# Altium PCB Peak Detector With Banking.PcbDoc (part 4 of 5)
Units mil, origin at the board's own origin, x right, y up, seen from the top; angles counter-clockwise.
Board outline 3330 x 2725 mil, 4 copper layers (TopLayer, GROUND, MidLayer1, BottomLayer); 549 components, 391 nets, 1594 pads, 460 vias.
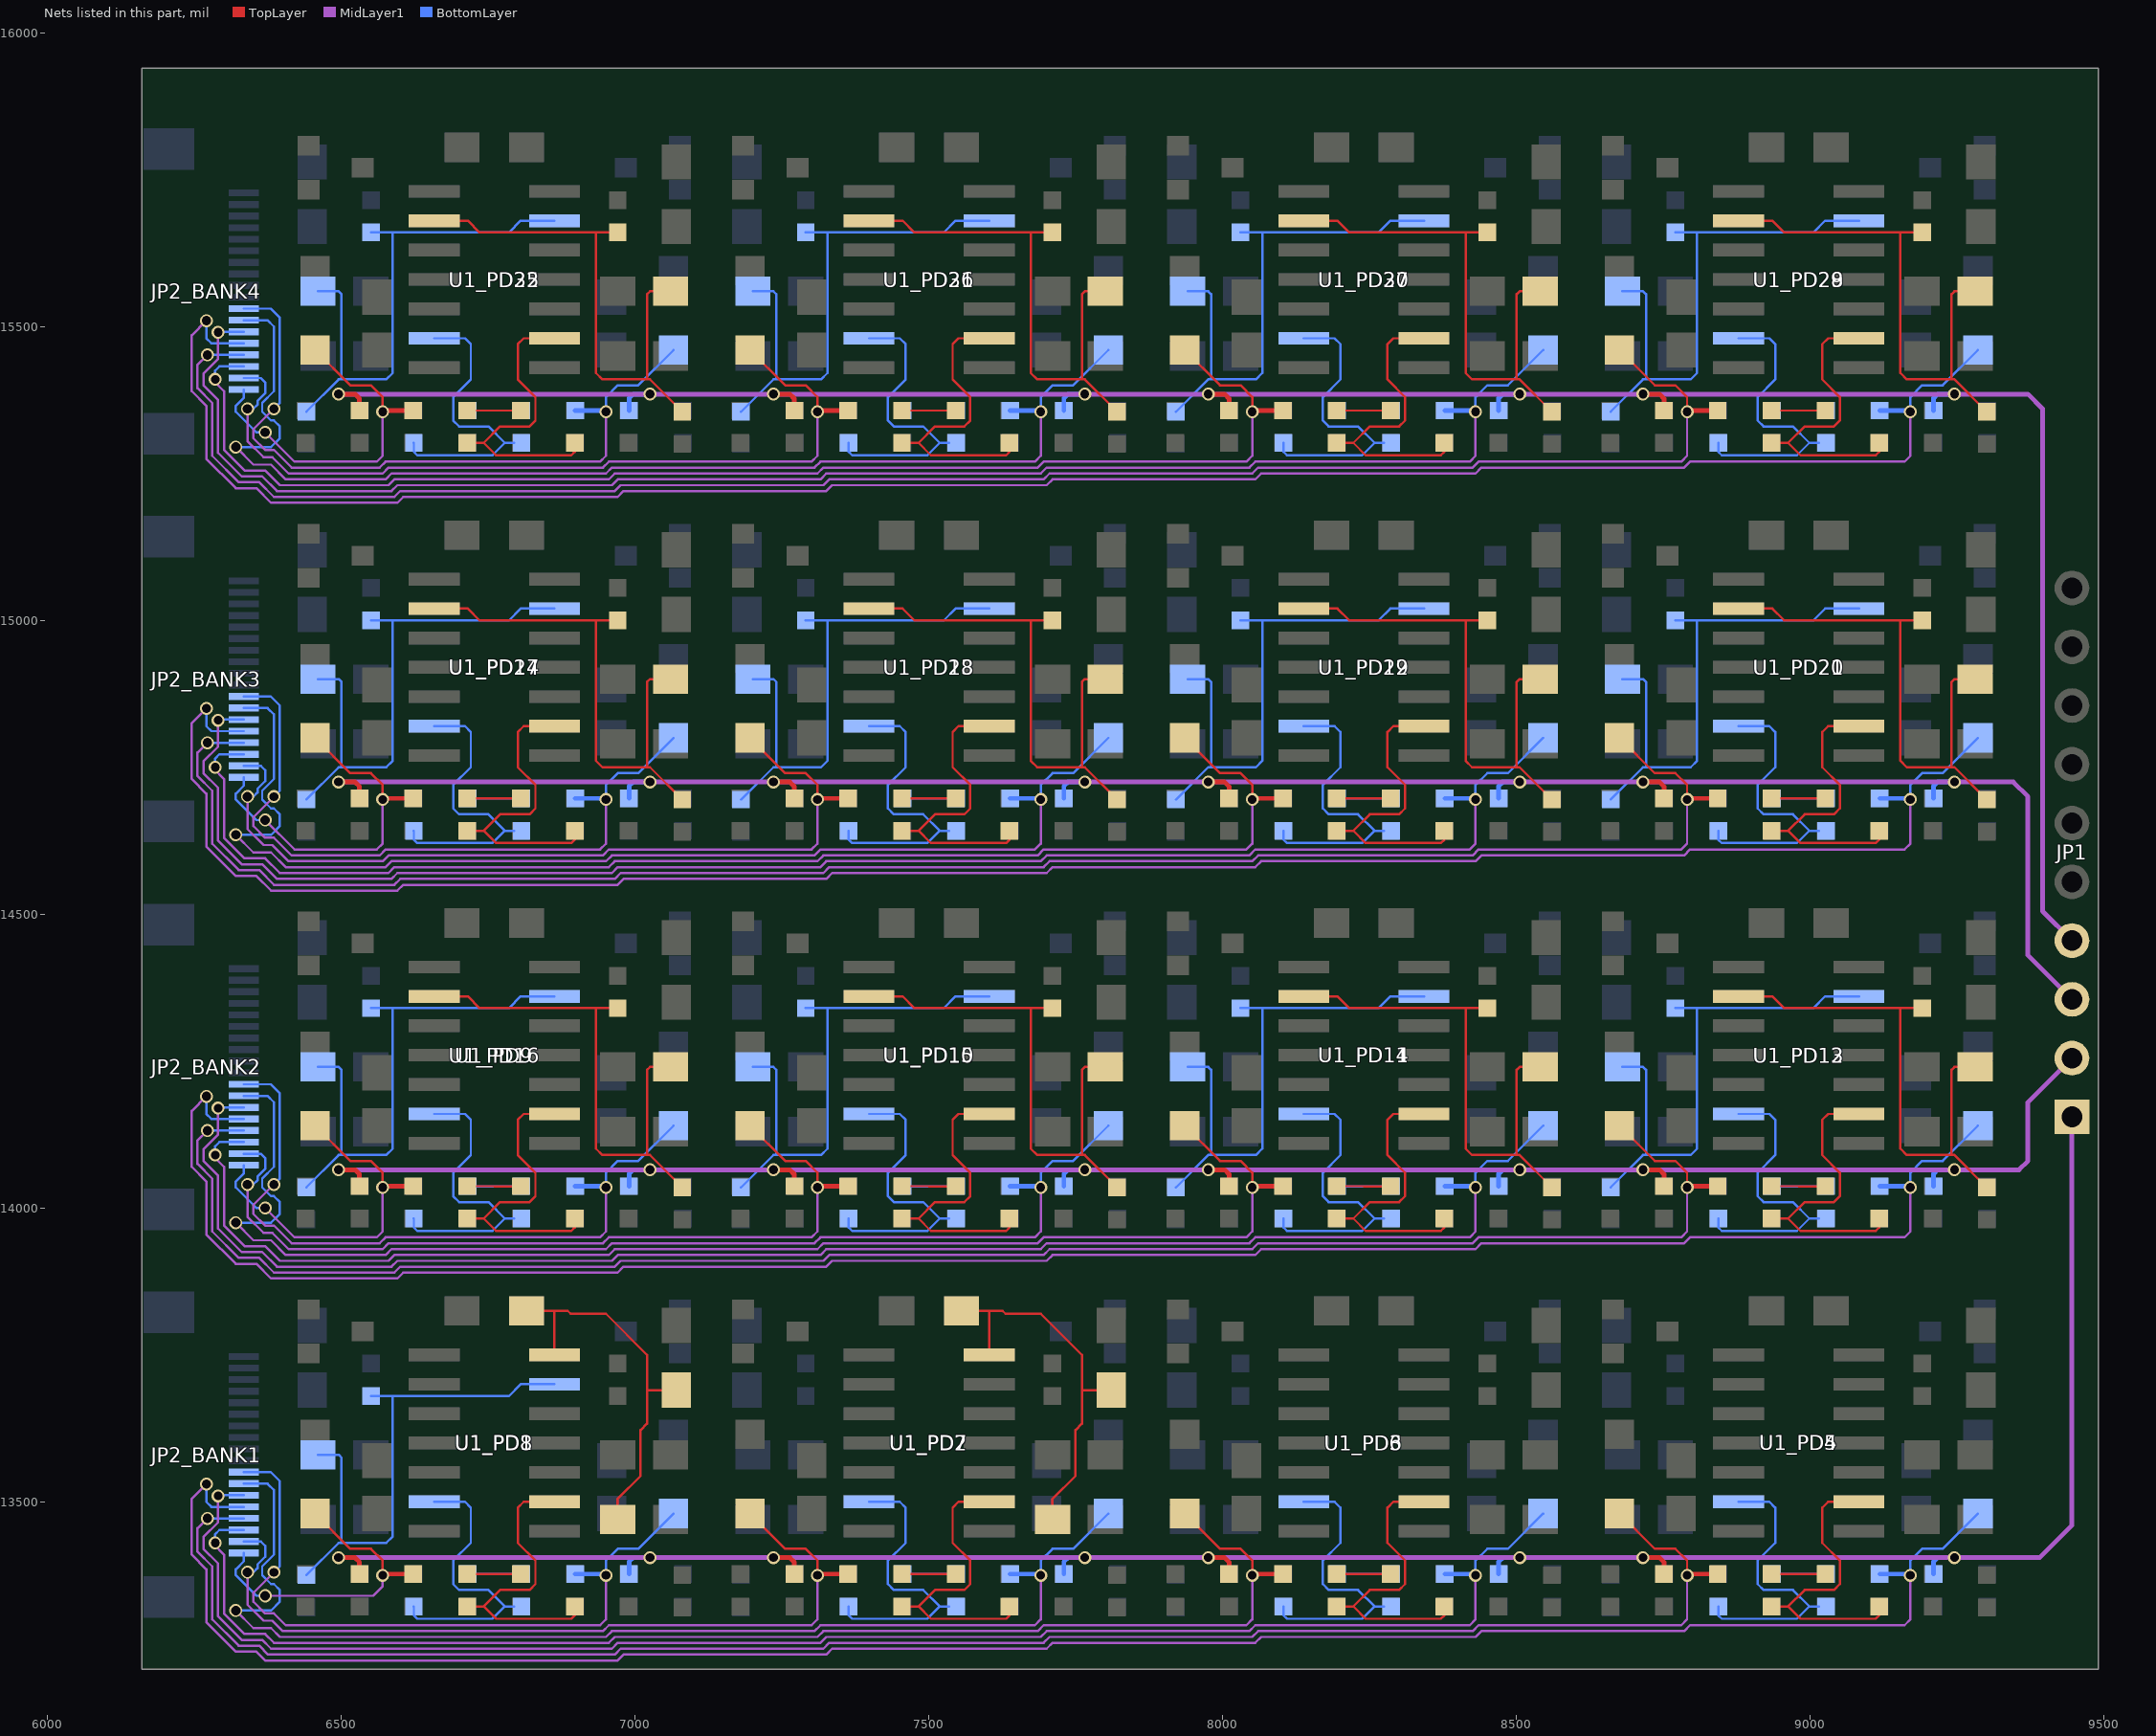
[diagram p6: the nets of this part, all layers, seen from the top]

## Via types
v1: diameter 22, hole 15, TopLayer to BottomLayer, 432 vias
v2: diameter 22, hole 16, TopLayer to BottomLayer, 28 vias

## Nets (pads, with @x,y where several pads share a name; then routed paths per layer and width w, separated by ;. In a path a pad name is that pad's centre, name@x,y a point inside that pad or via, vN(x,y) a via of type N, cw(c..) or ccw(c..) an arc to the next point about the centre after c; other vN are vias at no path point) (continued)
NetC5_PD8_2: C5_PD8.2 R8_PD8.2 R88_PD8.1 U1_PD8.9 | length 921.1
  BottomLayer w4: R8_PD8.2@6440,13375 6495,13430 6500,13430 ; C5_PD8.2@6459.99,13580 6495,13580 6500,13575 6500,13430 ; R88_PD8.1@6550,13680 6587,13680 ; U1_PD8.9@6862.37,13700 6805,13700 6785,13680 6587,13680 ; 6500,13430 6576,13430 6587,13441 6587,13680
NetC5_PD9_2: C5_PD9.2 R8_PD9.2 R88_PD9.1 U1_PD9.9 | length 921.1
  TopLayer w4: U1_PD9.9@6657.63,14360 6715,14360 6735,14340 6933,14340 ; R88_PD9.1@6970,14340 6933,14340 ; C5_PD9.2@7060.01,14240 7025,14240 7020,14235 7020,14090 ; R8_PD9.2@7080,14035 7025,14090 7020,14090 ; 6933,14340 6933,14101 6944,14090 7020,14090
NetC5_PD10_2: C5_PD10.2 R8_PD10.2 R88_PD10.1 U1_PD10.9 | length 921.1
  TopLayer w4: U1_PD10.9@7397.63,14360 7455,14360 7475,14340 7673,14340 ; R88_PD10.1@7710,14340 7673,14340 ; C5_PD10.2@7800.01,14240 7765,14240 7760,14235 7760,14090 ; R8_PD10.2@7820,14035 7765,14090 7760,14090 ; 7673,14340 7673,14101 7684,14090 7760,14090
NetC5_PD11_2: C5_PD11.2 R8_PD11.2 R88_PD11.1 U1_PD11.9 | length 921.1
  TopLayer w4: U1_PD11.9@8137.63,14360 8195,14360 8215,14340 8413,14340 ; R88_PD11.1@8450,14340 8413,14340 ; C5_PD11.2@8540.01,14240 8505,14240 8500,14235 8500,14090 ; R8_PD11.2@8560,14035 8505,14090 8500,14090 ; 8413,14340 8413,14101 8424,14090 8500,14090
NetC5_PD12_2: C5_PD12.2 R8_PD12.2 R88_PD12.1 U1_PD12.9 | length 921.1
  TopLayer w4: U1_PD12.9@8877.63,14360 8935,14360 8955,14340 9153,14340 ; R88_PD12.1@9190,14340 9153,14340 ; C5_PD12.2@9280.01,14240 9245,14240 9240,14235 9240,14090 ; R8_PD12.2@9300,14035 9245,14090 9240,14090 ; 9153,14340 9153,14101 9164,14090 9240,14090
NetC5_PD13_2: C5_PD13.2 R8_PD13.2 R88_PD13.1 U1_PD13.9 | length 921.1
  BottomLayer w4: R8_PD13.2@8660,14035 8715,14090 8720,14090 ; C5_PD13.2@8679.99,14240 8715,14240 8720,14235 8720,14090 ; R88_PD13.1@8770,14340 8807,14340 ; U1_PD13.9@9082.37,14360 9025,14360 9005,14340 8807,14340 ; 8720,14090 8796,14090 8807,14101 8807,14340
NetC5_PD14_2: C5_PD14.2 R8_PD14.2 R88_PD14.1 U1_PD14.9 | length 921.1
  BottomLayer w4: R8_PD14.2@7920,14035 7975,14090 7980,14090 ; C5_PD14.2@7939.99,14240 7975,14240 7980,14235 7980,14090 ; R88_PD14.1@8030,14340 8067,14340 ; U1_PD14.9@8342.37,14360 8285,14360 8265,14340 8067,14340 ; 7980,14090 8056,14090 8067,14101 8067,14340
NetC5_PD15_2: C5_PD15.2 R8_PD15.2 R88_PD15.1 U1_PD15.9 | length 921.1
  BottomLayer w4: R8_PD15.2@7180,14035 7235,14090 7240,14090 ; C5_PD15.2@7199.99,14240 7235,14240 7240,14235 7240,14090 ; R88_PD15.1@7290,14340 7327,14340 ; U1_PD15.9@7602.37,14360 7545,14360 7525,14340 7327,14340 ; 7240,14090 7316,14090 7327,14101 7327,14340
NetC5_PD16_2: C5_PD16.2 R8_PD16.2 R88_PD16.1 U1_PD16.9 | length 921.1
  BottomLayer w4: R8_PD16.2@6440,14035 6495,14090 6500,14090 ; C5_PD16.2@6459.99,14240 6495,14240 6500,14235 6500,14090 ; R88_PD16.1@6550,14340 6587,14340 ; U1_PD16.9@6862.37,14360 6805,14360 6785,14340 6587,14340 ; 6500,14090 6576,14090 6587,14101 6587,14340
NetC5_PD17_2: C5_PD17.2 R8_PD17.2 R88_PD17.1 U1_PD17.9 | length 921.1
  TopLayer w4: U1_PD17.9@6657.63,15020 6715,15020 6735,15000 6933,15000 ; R88_PD17.1@6970,15000 6933,15000 ; C5_PD17.2@7060.01,14900 7025,14900 7020,14895 7020,14750 ; R8_PD17.2@7080,14695 7025,14750 7020,14750 ; 6933,15000 6933,14761 6944,14750 7020,14750
NetC5_PD18_2: C5_PD18.2 R8_PD18.2 R88_PD18.1 U1_PD18.9 | length 921.1
  TopLayer w4: U1_PD18.9@7397.63,15020 7455,15020 7475,15000 7673,15000 ; R88_PD18.1@7710,15000 7673,15000 ; C5_PD18.2@7800.01,14900 7765,14900 7760,14895 7760,14750 ; R8_PD18.2@7820,14695 7765,14750 7760,14750 ; 7673,15000 7673,14761 7684,14750 7760,14750
NetC5_PD19_2: C5_PD19.2 R8_PD19.2 R88_PD19.1 U1_PD19.9 | length 921.1
  TopLayer w4: U1_PD19.9@8137.63,15020 8195,15020 8215,15000 8413,15000 ; R88_PD19.1@8450,15000 8413,15000 ; C5_PD19.2@8540.01,14900 8505,14900 8500,14895 8500,14750 ; R8_PD19.2@8560,14695 8505,14750 8500,14750 ; 8413,15000 8413,14761 8424,14750 8500,14750
NetC5_PD20_2: C5_PD20.2 R8_PD20.2 R88_PD20.1 U1_PD20.9 | length 921.1
  TopLayer w4: U1_PD20.9@8877.63,15020 8935,15020 8955,15000 9153,15000 ; R88_PD20.1@9190,15000 9153,15000 ; C5_PD20.2@9280.01,14900 9245,14900 9240,14895 9240,14750 ; R8_PD20.2@9300,14695 9245,14750 9240,14750 ; 9153,15000 9153,14761 9164,14750 9240,14750
NetC5_PD21_2: C5_PD21.2 R8_PD21.2 R88_PD21.1 U1_PD21.9 | length 921.1
  BottomLayer w4: R8_PD21.2@8660,14695 8715,14750 8720,14750 ; C5_PD21.2@8679.99,14900 8715,14900 8720,14895 8720,14750 ; R88_PD21.1@8770,15000 8807,15000 ; U1_PD21.9@9082.37,15020 9025,15020 9005,15000 8807,15000 ; 8720,14750 8796,14750 8807,14761 8807,15000
NetC5_PD22_2: C5_PD22.2 R8_PD22.2 R88_PD22.1 U1_PD22.9 | length 921.1
  BottomLayer w4: R8_PD22.2@7920,14695 7975,14750 7980,14750 ; C5_PD22.2@7939.99,14900 7975,14900 7980,14895 7980,14750 ; R88_PD22.1@8030,15000 8067,15000 ; U1_PD22.9@8342.37,15020 8285,15020 8265,15000 8067,15000 ; 7980,14750 8056,14750 8067,14761 8067,15000
NetC5_PD23_2: C5_PD23.2 R8_PD23.2 R88_PD23.1 U1_PD23.9 | length 921.1
  BottomLayer w4: R8_PD23.2@7180,14695 7235,14750 7240,14750 ; C5_PD23.2@7199.99,14900 7235,14900 7240,14895 7240,14750 ; R88_PD23.1@7290,15000 7327,15000 ; U1_PD23.9@7602.37,15020 7545,15020 7525,15000 7327,15000 ; 7240,14750 7316,14750 7327,14761 7327,15000
NetC5_PD24_2: C5_PD24.2 R8_PD24.2 R88_PD24.1 U1_PD24.9 | length 921.1
  BottomLayer w4: R8_PD24.2@6440,14695 6495,14750 6500,14750 ; C5_PD24.2@6459.99,14900 6495,14900 6500,14895 6500,14750 ; R88_PD24.1@6550,15000 6587,15000 ; U1_PD24.9@6862.37,15020 6805,15020 6785,15000 6587,15000 ; 6500,14750 6576,14750 6587,14761 6587,15000
NetC5_PD25_2: C5_PD25.2 R8_PD25.2 R88_PD25.1 U1_PD25.9 | length 921.1
  TopLayer w4: U1_PD25.9@6657.63,15680 6715,15680 6735,15660 6933,15660 ; R88_PD25.1@6970,15660 6933,15660 ; C5_PD25.2@7060.01,15560 7025,15560 7020,15555 7020,15410 ; R8_PD25.2@7080,15355 7025,15410 7020,15410 ; 6933,15660 6933,15421 6944,15410 7020,15410
NetC5_PD26_2: C5_PD26.2 R8_PD26.2 R88_PD26.1 U1_PD26.9 | length 921.1
  TopLayer w4: U1_PD26.9@7397.63,15680 7455,15680 7475,15660 7673,15660 ; R88_PD26.1@7710,15660 7673,15660 ; C5_PD26.2@7800.01,15560 7765,15560 7760,15555 7760,15410 ; R8_PD26.2@7820,15355 7765,15410 7760,15410 ; 7673,15660 7673,15421 7684,15410 7760,15410
NetC5_PD27_2: C5_PD27.2 R8_PD27.2 R88_PD27.1 U1_PD27.9 | length 921.1
  TopLayer w4: U1_PD27.9@8137.63,15680 8195,15680 8215,15660 8413,15660 ; R88_PD27.1@8450,15660 8413,15660 ; C5_PD27.2@8540.01,15560 8505,15560 8500,15555 8500,15410 ; R8_PD27.2@8560,15355 8505,15410 8500,15410 ; 8413,15660 8413,15421 8424,15410 8500,15410
NetC5_PD28_2: C5_PD28.2 R8_PD28.2 R88_PD28.1 U1_PD28.9 | length 921.1
  TopLayer w4: U1_PD28.9@8877.63,15680 8935,15680 8955,15660 9153,15660 ; R88_PD28.1@9190,15660 9153,15660 ; C5_PD28.2@9280.01,15560 9245,15560 9240,15555 9240,15410 ; R8_PD28.2@9300,15355 9245,15410 9240,15410 ; 9153,15660 9153,15421 9164,15410 9240,15410
NetC5_PD29_2: C5_PD29.2 R8_PD29.2 R88_PD29.1 U1_PD29.9 | length 921.1
  BottomLayer w4: R8_PD29.2@8660,15355 8715,15410 8720,15410 ; C5_PD29.2@8679.99,15560 8715,15560 8720,15555 8720,15410 ; R88_PD29.1@8770,15660 8807,15660 ; U1_PD29.9@9082.37,15680 9025,15680 9005,15660 8807,15660 ; 8720,15410 8796,15410 8807,15421 8807,15660
NetC5_PD30_2: C5_PD30.2 R8_PD30.2 R88_PD30.1 U1_PD30.9 | length 921.1
  BottomLayer w4: R8_PD30.2@7920,15355 7975,15410 7980,15410 ; C5_PD30.2@7939.99,15560 7975,15560 7980,15555 7980,15410 ; R88_PD30.1@8030,15660 8067,15660 ; U1_PD30.9@8342.37,15680 8285,15680 8265,15660 8067,15660 ; 7980,15410 8056,15410 8067,15421 8067,15660
NetC5_PD31_2: C5_PD31.2 R8_PD31.2 R88_PD31.1 U1_PD31.9 | length 921.1
  BottomLayer w4: R8_PD31.2@7180,15355 7235,15410 7240,15410 ; C5_PD31.2@7199.99,15560 7235,15560 7240,15555 7240,15410 ; R88_PD31.1@7290,15660 7327,15660 ; U1_PD31.9@7602.37,15680 7545,15680 7525,15660 7327,15660 ; 7240,15410 7316,15410 7327,15421 7327,15660
NetC5_PD32_2: C5_PD32.2 R8_PD32.2 R88_PD32.1 U1_PD32.9 | length 921.1
  BottomLayer w4: R8_PD32.2@6440,15355 6495,15410 6500,15410 ; C5_PD32.2@6459.99,15560 6495,15560 6500,15555 6500,15410 ; R88_PD32.1@6550,15660 6587,15660 ; U1_PD32.9@6862.37,15680 6805,15680 6785,15660 6587,15660 ; 6500,15410 6576,15410 6587,15421 6587,15660
NetR1_PD1_2: R1_PD1.2 R2_PD1.2 U1_PD1.2 | length 510
  TopLayer w4: R2_PD1.2@6726,13322 6742,13322 ; U1_PD1.2@6862.35,13500 6810,13500 6800,13490 6800,13430 6830,13400 6830,13360 6820,13350 6770,13350 6742,13322 ; R1_PD1.2@6897,13321.99 R1_PD1.2@6896.86,13321.99 6896.86,13306.86 6890.93,13300.93 6763.07,13300.93 6742,13322
NetR1_PD2_2: R1_PD2.2 R2_PD2.2 U1_PD2.2 | length 510
  TopLayer w4: R2_PD2.2@7466,13322 7482,13322 ; U1_PD2.2@7602.35,13500 7550,13500 7540,13490 7540,13430 7570,13400 7570,13360 7560,13350 7510,13350 7482,13322 ; R1_PD2.2@7637,13321.99 R1_PD2.2@7636.86,13321.99 7636.86,13306.86 7630.93,13300.93 7503.07,13300.93 7482,13322
NetR1_PD3_2: R1_PD3.2 R2_PD3.2 U1_PD3.2 | length 510
  TopLayer w4: R2_PD3.2@8206,13322 8222,13322 ; U1_PD3.2@8342.35,13500 8290,13500 8280,13490 8280,13430 8310,13400 8310,13360 8300,13350 8250,13350 8222,13322 ; R1_PD3.2@8377,13321.99 R1_PD3.2@8376.86,13321.99 8376.86,13306.86 8370.93,13300.93 8243.07,13300.93 8222,13322
NetR1_PD4_2: R1_PD4.2 R2_PD4.2 U1_PD4.2 | length 510
  TopLayer w4: R2_PD4.2@8946,13322 8962,13322 ; U1_PD4.2@9082.35,13500 9030,13500 9020,13490 9020,13430 9050,13400 9050,13360 9040,13350 8990,13350 8962,13322 ; R1_PD4.2@9117,13321.99 R1_PD4.2@9116.86,13321.99 9116.86,13306.86 9110.93,13300.93 8983.07,13300.93 8962,13322
NetR1_PD5_2: R1_PD5.2 R2_PD5.2 U1_PD5.2 | length 510
  BottomLayer w4: R1_PD5.2@8843,13321.99 R1_PD5.2@8843.14,13321.99 8843.14,13306.86 8849.07,13300.93 8976.93,13300.93 8998,13322 ; U1_PD5.2@8877.65,13500 8930,13500 8940,13490 8940,13430 8910,13400 8910,13360 8920,13350 8970,13350 8998,13322 ; R2_PD5.2@9014,13322 8998,13322
NetR1_PD6_2: R1_PD6.2 R2_PD6.2 U1_PD6.2 | length 510
  BottomLayer w4: R1_PD6.2@8103,13321.99 R1_PD6.2@8103.14,13321.99 8103.14,13306.86 8109.07,13300.93 8236.93,13300.93 8258,13322 ; U1_PD6.2@8137.65,13500 8190,13500 8200,13490 8200,13430 8170,13400 8170,13360 8180,13350 8230,13350 8258,13322 ; R2_PD6.2@8274,13322 8258,13322
NetR1_PD7_2: R1_PD7.2 R2_PD7.2 U1_PD7.2 | length 510
  BottomLayer w4: R1_PD7.2@7363,13321.99 R1_PD7.2@7363.14,13321.99 7363.14,13306.86 7369.07,13300.93 7496.93,13300.93 7518,13322 ; U1_PD7.2@7397.65,13500 7450,13500 7460,13490 7460,13430 7430,13400 7430,13360 7440,13350 7490,13350 7518,13322 ; R2_PD7.2@7534,13322 7518,13322
NetR1_PD8_2: R1_PD8.2 R2_PD8.2 U1_PD8.2 | length 510
  BottomLayer w4: R1_PD8.2@6623,13321.99 R1_PD8.2@6623.14,13321.99 6623.14,13306.86 6629.07,13300.93 6756.93,13300.93 6778,13322 ; U1_PD8.2@6657.65,13500 6710,13500 6720,13490 6720,13430 6690,13400 6690,13360 6700,13350 6750,13350 6778,13322 ; R2_PD8.2@6794,13322 6778,13322
NetR1_PD9_2: R1_PD9.2 R2_PD9.2 U1_PD9.2 | length 510
  TopLayer w4: R2_PD9.2@6726,13982 6742,13982 ; U1_PD9.2@6862.35,14160 6810,14160 6800,14150 6800,14090 6830,14060 6830,14020 6820,14010 6770,14010 6742,13982 ; R1_PD9.2@6897,13981.99 R1_PD9.2@6896.86,13981.99 6896.86,13966.86 6890.93,13960.93 6763.07,13960.93 6742,13982
NetR1_PD10_2: R1_PD10.2 R2_PD10.2 U1_PD10.2 | length 510
  TopLayer w4: R2_PD10.2@7466,13982 7482,13982 ; U1_PD10.2@7602.35,14160 7550,14160 7540,14150 7540,14090 7570,14060 7570,14020 7560,14010 7510,14010 7482,13982 ; R1_PD10.2@7637,13981.99 R1_PD10.2@7636.86,13981.99 7636.86,13966.86 7630.93,13960.93 7503.07,13960.93 7482,13982
NetR1_PD11_2: R1_PD11.2 R2_PD11.2 U1_PD11.2 | length 510
  TopLayer w4: R2_PD11.2@8206,13982 8222,13982 ; U1_PD11.2@8342.35,14160 8290,14160 8280,14150 8280,14090 8310,14060 8310,14020 8300,14010 8250,14010 8222,13982 ; R1_PD11.2@8377,13981.99 R1_PD11.2@8376.86,13981.99 8376.86,13966.86 8370.93,13960.93 8243.07,13960.93 8222,13982
NetR1_PD12_2: R1_PD12.2 R2_PD12.2 U1_PD12.2 | length 510
  TopLayer w4: R2_PD12.2@8946,13982 8962,13982 ; U1_PD12.2@9082.35,14160 9030,14160 9020,14150 9020,14090 9050,14060 9050,14020 9040,14010 8990,14010 8962,13982 ; R1_PD12.2@9117,13981.99 R1_PD12.2@9116.86,13981.99 9116.86,13966.86 9110.93,13960.93 8983.07,13960.93 8962,13982
NetR1_PD13_2: R1_PD13.2 R2_PD13.2 U1_PD13.2 | length 510
  BottomLayer w4: R1_PD13.2@8843,13981.99 R1_PD13.2@8843.14,13981.99 8843.14,13966.86 8849.07,13960.93 8976.93,13960.93 8998,13982 ; U1_PD13.2@8877.65,14160 8930,14160 8940,14150 8940,14090 8910,14060 8910,14020 8920,14010 8970,14010 8998,13982 ; R2_PD13.2@9014,13982 8998,13982
NetR1_PD14_2: R1_PD14.2 R2_PD14.2 U1_PD14.2 | length 510
  BottomLayer w4: R1_PD14.2@8103,13981.99 R1_PD14.2@8103.14,13981.99 8103.14,13966.86 8109.07,13960.93 8236.93,13960.93 8258,13982 ; U1_PD14.2@8137.65,14160 8190,14160 8200,14150 8200,14090 8170,14060 8170,14020 8180,14010 8230,14010 8258,13982 ; R2_PD14.2@8274,13982 8258,13982
NetR1_PD15_2: R1_PD15.2 R2_PD15.2 U1_PD15.2 | length 510
  BottomLayer w4: R1_PD15.2@7363,13981.99 R1_PD15.2@7363.14,13981.99 7363.14,13966.86 7369.07,13960.93 7496.93,13960.93 7518,13982 ; U1_PD15.2@7397.65,14160 7450,14160 7460,14150 7460,14090 7430,14060 7430,14020 7440,14010 7490,14010 7518,13982 ; R2_PD15.2@7534,13982 7518,13982
NetR1_PD16_2: R1_PD16.2 R2_PD16.2 U1_PD16.2 | length 510
  BottomLayer w4: R1_PD16.2@6623,13981.99 R1_PD16.2@6623.14,13981.99 6623.14,13966.86 6629.07,13960.93 6756.93,13960.93 6778,13982 ; U1_PD16.2@6657.65,14160 6710,14160 6720,14150 6720,14090 6690,14060 6690,14020 6700,14010 6750,14010 6778,13982 ; R2_PD16.2@6794,13982 6778,13982
NetR1_PD17_2: R1_PD17.2 R2_PD17.2 U1_PD17.2 | length 510
  TopLayer w4: R2_PD17.2@6726,14642 6742,14642 ; U1_PD17.2@6862.35,14820 6810,14820 6800,14810 6800,14750 6830,14720 6830,14680 6820,14670 6770,14670 6742,14642 ; R1_PD17.2@6897,14641.99 R1_PD17.2@6896.86,14641.99 6896.86,14626.86 6890.93,14620.93 6763.07,14620.93 6742,14642
NetR1_PD18_2: R1_PD18.2 R2_PD18.2 U1_PD18.2 | length 510
  TopLayer w4: R2_PD18.2@7466,14642 7482,14642 ; U1_PD18.2@7602.35,14820 7550,14820 7540,14810 7540,14750 7570,14720 7570,14680 7560,14670 7510,14670 7482,14642 ; R1_PD18.2@7637,14641.99 R1_PD18.2@7636.86,14641.99 7636.86,14626.86 7630.93,14620.93 7503.07,14620.93 7482,14642
NetR1_PD19_2: R1_PD19.2 R2_PD19.2 U1_PD19.2 | length 510
  TopLayer w4: R2_PD19.2@8206,14642 8222,14642 ; U1_PD19.2@8342.35,14820 8290,14820 8280,14810 8280,14750 8310,14720 8310,14680 8300,14670 8250,14670 8222,14642 ; R1_PD19.2@8377,14641.99 R1_PD19.2@8376.86,14641.99 8376.86,14626.86 8370.93,14620.93 8243.07,14620.93 8222,14642
NetR1_PD20_2: R1_PD20.2 R2_PD20.2 U1_PD20.2 | length 510
  TopLayer w4: R2_PD20.2@8946,14642 8962,14642 ; U1_PD20.2@9082.35,14820 9030,14820 9020,14810 9020,14750 9050,14720 9050,14680 9040,14670 8990,14670 8962,14642 ; R1_PD20.2@9117,14641.99 R1_PD20.2@9116.86,14641.99 9116.86,14626.86 9110.93,14620.93 8983.07,14620.93 8962,14642
NetR1_PD21_2: R1_PD21.2 R2_PD21.2 U1_PD21.2 | length 510
  BottomLayer w4: R1_PD21.2@8843,14641.99 R1_PD21.2@8843.14,14641.99 8843.14,14626.86 8849.07,14620.93 8976.93,14620.93 8998,14642 ; U1_PD21.2@8877.65,14820 8930,14820 8940,14810 8940,14750 8910,14720 8910,14680 8920,14670 8970,14670 8998,14642 ; R2_PD21.2@9014,14642 8998,14642
NetR1_PD22_2: R1_PD22.2 R2_PD22.2 U1_PD22.2 | length 510
  BottomLayer w4: R1_PD22.2@8103,14641.99 R1_PD22.2@8103.14,14641.99 8103.14,14626.86 8109.07,14620.93 8236.93,14620.93 8258,14642 ; U1_PD22.2@8137.65,14820 8190,14820 8200,14810 8200,14750 8170,14720 8170,14680 8180,14670 8230,14670 8258,14642 ; R2_PD22.2@8274,14642 8258,14642
NetR1_PD23_2: R1_PD23.2 R2_PD23.2 U1_PD23.2 | length 510
  BottomLayer w4: R1_PD23.2@7363,14641.99 R1_PD23.2@7363.14,14641.99 7363.14,14626.86 7369.07,14620.93 7496.93,14620.93 7518,14642 ; U1_PD23.2@7397.65,14820 7450,14820 7460,14810 7460,14750 7430,14720 7430,14680 7440,14670 7490,14670 7518,14642 ; R2_PD23.2@7534,14642 7518,14642
NetR1_PD24_2: R1_PD24.2 R2_PD24.2 U1_PD24.2 | length 510
  BottomLayer w4: R1_PD24.2@6623,14641.99 R1_PD24.2@6623.14,14641.99 6623.14,14626.86 6629.07,14620.93 6756.93,14620.93 6778,14642 ; U1_PD24.2@6657.65,14820 6710,14820 6720,14810 6720,14750 6690,14720 6690,14680 6700,14670 6750,14670 6778,14642 ; R2_PD24.2@6794,14642 6778,14642
NetR1_PD25_2: R1_PD25.2 R2_PD25.2 U1_PD25.2 | length 510
  TopLayer w4: R2_PD25.2@6726,15302 6742,15302 ; U1_PD25.2@6862.35,15480 6810,15480 6800,15470 6800,15410 6830,15380 6830,15340 6820,15330 6770,15330 6742,15302 ; R1_PD25.2@6897,15301.99 R1_PD25.2@6896.86,15301.99 6896.86,15286.86 6890.93,15280.93 6763.07,15280.93 6742,15302
NetR1_PD26_2: R1_PD26.2 R2_PD26.2 U1_PD26.2 | length 510
  TopLayer w4: R2_PD26.2@7466,15302 7482,15302 ; U1_PD26.2@7602.35,15480 7550,15480 7540,15470 7540,15410 7570,15380 7570,15340 7560,15330 7510,15330 7482,15302 ; R1_PD26.2@7637,15301.99 R1_PD26.2@7636.86,15301.99 7636.86,15286.86 7630.93,15280.93 7503.07,15280.93 7482,15302
NetR1_PD27_2: R1_PD27.2 R2_PD27.2 U1_PD27.2 | length 510
  TopLayer w4: R2_PD27.2@8206,15302 8222,15302 ; U1_PD27.2@8342.35,15480 8290,15480 8280,15470 8280,15410 8310,15380 8310,15340 8300,15330 8250,15330 8222,15302 ; R1_PD27.2@8377,15301.99 R1_PD27.2@8376.86,15301.99 8376.86,15286.86 8370.93,15280.93 8243.07,15280.93 8222,15302
NetR1_PD28_2: R1_PD28.2 R2_PD28.2 U1_PD28.2 | length 510
  TopLayer w4: R2_PD28.2@8946,15302 8962,15302 ; U1_PD28.2@9082.35,15480 9030,15480 9020,15470 9020,15410 9050,15380 9050,15340 9040,15330 8990,15330 8962,15302 ; R1_PD28.2@9117,15301.99 R1_PD28.2@9116.86,15301.99 9116.86,15286.86 9110.93,15280.93 8983.07,15280.93 8962,15302
NetR1_PD29_2: R1_PD29.2 R2_PD29.2 U1_PD29.2 | length 510
  BottomLayer w4: R1_PD29.2@8843,15301.99 R1_PD29.2@8843.14,15301.99 8843.14,15286.86 8849.07,15280.93 8976.93,15280.93 8998,15302 ; U1_PD29.2@8877.65,15480 8930,15480 8940,15470 8940,15410 8910,15380 8910,15340 8920,15330 8970,15330 8998,15302 ; R2_PD29.2@9014,15302 8998,15302
NetR1_PD30_2: R1_PD30.2 R2_PD30.2 U1_PD30.2 | length 510
  BottomLayer w4: R1_PD30.2@8103,15301.99 R1_PD30.2@8103.14,15301.99 8103.14,15286.86 8109.07,15280.93 8236.93,15280.93 8258,15302 ; U1_PD30.2@8137.65,15480 8190,15480 8200,15470 8200,15410 8170,15380 8170,15340 8180,15330 8230,15330 8258,15302 ; R2_PD30.2@8274,15302 8258,15302
NetR1_PD31_2: R1_PD31.2 R2_PD31.2 U1_PD31.2 | length 510
  BottomLayer w4: R1_PD31.2@7363,15301.99 R1_PD31.2@7363.14,15301.99 7363.14,15286.86 7369.07,15280.93 7496.93,15280.93 7518,15302 ; U1_PD31.2@7397.65,15480 7450,15480 7460,15470 7460,15410 7430,15380 7430,15340 7440,15330 7490,15330 7518,15302 ; R2_PD31.2@7534,15302 7518,15302
NetR1_PD32_2: R1_PD32.2 R2_PD32.2 U1_PD32.2 | length 510
  BottomLayer w4: R1_PD32.2@6623,15301.99 R1_PD32.2@6623.14,15301.99 6623.14,15286.86 6629.07,15280.93 6756.93,15280.93 6778,15302 ; U1_PD32.2@6657.65,15480 6710,15480 6720,15470 6720,15410 6690,15380 6690,15340 6700,15330 6750,15330 6778,15302 ; R2_PD32.2@6794,15302 6778,15302
NetR2_PD1_1: R2_PD1.1 RPOT_PD1.1 | length 91.6
  TopLayer w4: R2_PD1.1@6713.71,13376.99 6760,13377 RPOT_PD1.1@6805.29,13376.99
NetR2_PD2_1: R2_PD2.1 RPOT_PD2.1 | length 91.6
  TopLayer w4: R2_PD2.1@7453.71,13376.99 7500,13377 RPOT_PD2.1@7545.29,13376.99
NetR2_PD3_1: R2_PD3.1 RPOT_PD3.1 | length 91.6
  TopLayer w4: R2_PD3.1@8193.71,13376.99 8240,13377 RPOT_PD3.1@8285.29,13376.99
NetR2_PD4_1: R2_PD4.1 RPOT_PD4.1 | length 91.6
  TopLayer w4: R2_PD4.1@8933.71,13376.99 8980,13377 RPOT_PD4.1@9025.29,13376.99
NetR2_PD5_1: R2_PD5.1 RPOT_PD5.1 | length 91.6
  BottomLayer w4: RPOT_PD5.1@8934.71,13376.99 8980,13376.99 R2_PD5.1@9026.29,13376.99
NetR2_PD6_1: R2_PD6.1 RPOT_PD6.1 | length 91.6
  BottomLayer w4: RPOT_PD6.1@8194.71,13376.99 8240,13376.99 R2_PD6.1@8286.29,13376.99
NetR2_PD7_1: R2_PD7.1 RPOT_PD7.1 | length 91.6
  BottomLayer w4: RPOT_PD7.1@7454.71,13376.99 7500,13376.99 R2_PD7.1@7546.29,13376.99
NetR2_PD8_1: R2_PD8.1 RPOT_PD8.1 | length 91.6
  BottomLayer w4: RPOT_PD8.1@6714.71,13376.99 6760,13376.99 R2_PD8.1@6806.29,13376.99
NetR2_PD9_1: R2_PD9.1 RPOT_PD9.1 | length 91.6
  TopLayer w4: R2_PD9.1@6713.71,14036.99 6760,14037 RPOT_PD9.1@6805.29,14036.99
NetR2_PD10_1: R2_PD10.1 RPOT_PD10.1 | length 91.6
  TopLayer w4: R2_PD10.1@7453.71,14036.99 7500,14037 RPOT_PD10.1@7545.29,14036.99
NetR2_PD11_1: R2_PD11.1 RPOT_PD11.1 | length 91.6
  TopLayer w4: R2_PD11.1@8193.71,14036.99 8240,14037 RPOT_PD11.1@8285.29,14036.99
NetR2_PD12_1: R2_PD12.1 RPOT_PD12.1 | length 91.6
  TopLayer w4: R2_PD12.1@8933.71,14036.99 8980,14037 RPOT_PD12.1@9025.29,14036.99
NetR2_PD13_1: R2_PD13.1 RPOT_PD13.1 | length 91.6
  BottomLayer w4: RPOT_PD13.1@8934.71,14036.99 8980,14036.99 R2_PD13.1@9026.29,14036.99
NetR2_PD14_1: R2_PD14.1 RPOT_PD14.1 | length 91.6
  BottomLayer w4: RPOT_PD14.1@8194.71,14036.99 8240,14036.99 R2_PD14.1@8286.29,14036.99
NetR2_PD15_1: R2_PD15.1 RPOT_PD15.1 | length 91.6
  BottomLayer w4: RPOT_PD15.1@7454.71,14036.99 7500,14036.99 R2_PD15.1@7546.29,14036.99
NetR2_PD16_1: R2_PD16.1 RPOT_PD16.1 | length 91.6
  BottomLayer w4: RPOT_PD16.1@6714.71,14036.99 6760,14036.99 R2_PD16.1@6806.29,14036.99
NetR2_PD17_1: R2_PD17.1 RPOT_PD17.1 | length 91.6
  TopLayer w4: R2_PD17.1@6713.71,14696.99 6760,14697 RPOT_PD17.1@6805.29,14696.99
NetR2_PD18_1: R2_PD18.1 RPOT_PD18.1 | length 91.6
  TopLayer w4: R2_PD18.1@7453.71,14696.99 7500,14697 RPOT_PD18.1@7545.29,14696.99
NetR2_PD19_1: R2_PD19.1 RPOT_PD19.1 | length 91.6
  TopLayer w4: R2_PD19.1@8193.71,14696.99 8240,14697 RPOT_PD19.1@8285.29,14696.99
NetR2_PD20_1: R2_PD20.1 RPOT_PD20.1 | length 91.6
  TopLayer w4: R2_PD20.1@8933.71,14696.99 8980,14697 RPOT_PD20.1@9025.29,14696.99
NetR2_PD21_1: R2_PD21.1 RPOT_PD21.1 | length 91.6
  BottomLayer w4: RPOT_PD21.1@8934.71,14696.99 8980,14696.99 R2_PD21.1@9026.29,14696.99
NetR2_PD22_1: R2_PD22.1 RPOT_PD22.1 | length 91.6
  BottomLayer w4: RPOT_PD22.1@8194.71,14696.99 8240,14696.99 R2_PD22.1@8286.29,14696.99
NetR2_PD23_1: R2_PD23.1 RPOT_PD23.1 | length 91.6
  BottomLayer w4: RPOT_PD23.1@7454.71,14696.99 7500,14696.99 R2_PD23.1@7546.29,14696.99
NetR2_PD24_1: R2_PD24.1 RPOT_PD24.1 | length 91.6
  BottomLayer w4: RPOT_PD24.1@6714.71,14696.99 6760,14696.99 R2_PD24.1@6806.29,14696.99
NetR2_PD25_1: R2_PD25.1 RPOT_PD25.1 | length 91.6
  TopLayer w4: R2_PD25.1@6713.71,15356.99 6760,15357 RPOT_PD25.1@6805.29,15356.99
NetR2_PD26_1: R2_PD26.1 RPOT_PD26.1 | length 91.6
  TopLayer w4: R2_PD26.1@7453.71,15356.99 7500,15357 RPOT_PD26.1@7545.29,15356.99
NetR2_PD27_1: R2_PD27.1 RPOT_PD27.1 | length 91.6
  TopLayer w4: R2_PD27.1@8193.71,15356.99 8240,15357 RPOT_PD27.1@8285.29,15356.99
NetR2_PD28_1: R2_PD28.1 RPOT_PD28.1 | length 91.6
  TopLayer w4: R2_PD28.1@8933.71,15356.99 8980,15357 RPOT_PD28.1@9025.29,15356.99
NetR2_PD29_1: R2_PD29.1 RPOT_PD29.1 | length 91.6
  BottomLayer w4: RPOT_PD29.1@8934.71,15356.99 8980,15356.99 R2_PD29.1@9026.29,15356.99
NetR2_PD30_1: R2_PD30.1 RPOT_PD30.1 | length 91.6
  BottomLayer w4: RPOT_PD30.1@8194.71,15356.99 8240,15356.99 R2_PD30.1@8286.29,15356.99
NetR2_PD31_1: R2_PD31.1 RPOT_PD31.1 | length 91.6
  BottomLayer w4: RPOT_PD31.1@7454.71,15356.99 7500,15356.99 R2_PD31.1@7546.29,15356.99
NetR2_PD32_1: R2_PD32.1 RPOT_PD32.1 | length 91.6
  BottomLayer w4: RPOT_PD32.1@6714.71,15356.99 6760,15356.99 R2_PD32.1@6806.29,15356.99
OFF1: JP1.1 R4_PD1.1 R4_PD2.1 R4_PD3.1 R4_PD4.1 R4_PD5.1 R4_PD6.1 R4_PD7.1 R4_PD8.1 | length 4142.3
  TopLayer w8: v1(6495,13405) 6523,13405 6530.57,13397.43 R4_PD1.1@6530.57,13376.99 ; v1(7235,13405) 7263,13405 7270.57,13397.43 R4_PD2.1@7270.57,13376.99 ; v1(7975,13405) 8003,13405 8010.57,13397.43 R4_PD3.1@8010.57,13376.99 ; v1(8715,13405) 8743,13405 8750.57,13397.43 R4_PD4.1@8750.57,13376.99
  MidLayer1 w8: v1(6495,13405) v1(7025,13405) v1(7235,13405) v1(7765,13405) v1(7975,13405) v1(8505,13405) v1(8715,13405) v1(9245,13405) 9390,13405 9445,13460 JP1.1@9445,14155
  BottomLayer w8: R4_PD8.1@6989.43,13376.99 6989.43,13398 6996.43,13405 v1(7025,13405) ; R4_PD7.1@7729.43,13376.99 7729.43,13398 7736.43,13405 v1(7765,13405) ; R4_PD6.1@8469.43,13376.99 8469.43,13398 8476.43,13405 v1(8505,13405) ; R4_PD5.1@9209.43,13376.99 9209.43,13398 9216.43,13405 v1(9245,13405)
OFF2: JP1.2 R4_PD9.1 R4_PD10.1 R4_PD11.1 R4_PD12.1 R4_PD13.1 R4_PD14.1 R4_PD15.1 R4_PD16.1 | length 3561.8
  TopLayer w8: v1(6495,14065) 6523,14065 6530.57,14057.43 R4_PD9.1@6530.57,14036.99 ; v1(7235,14065) 7263,14065 7270.57,14057.43 R4_PD10.1@7270.57,14036.99 ; v1(7975,14065) 8003,14065 8010.57,14057.43 R4_PD11.1@8010.57,14036.99 ; v1(8715,14065) 8743,14065 8750.57,14057.43 R4_PD12.1@8750.57,14036.99
  MidLayer1 w8: v1(6495,14065) v1(7025,14065) v1(7235,14065) v1(7765,14065) v1(7975,14065) v1(8505,14065) v1(8715,14065) v1(9245,14065) 9355,14065 9370,14080 9370,14180 JP1.2@9445,14255
  BottomLayer w8: R4_PD16.1@6989.43,14036.99 6989.43,14058 6996.43,14065 v1(7025,14065) ; R4_PD15.1@7729.43,14036.99 7729.43,14058 7736.43,14065 v1(7765,14065) ; R4_PD14.1@8469.43,14036.99 8469.43,14058 8476.43,14065 v1(8505,14065) ; R4_PD13.1@9209.43,14036.99 9209.43,14058 9216.43,14065 v1(9245,14065)
OFF3: JP1.3 R4_PD17.1 R4_PD18.1 R4_PD19.1 R4_PD20.1 R4_PD21.1 R4_PD22.1 R4_PD23.1 R4_PD24.1 | length 3735.9
  TopLayer w8: v1(6495,14725) 6523,14725 6530.57,14717.43 R4_PD17.1@6530.57,14696.99 ; v1(7235,14725) 7263,14725 7270.57,14717.43 R4_PD18.1@7270.57,14696.99 ; v1(7975,14725) 8003,14725 8010.57,14717.43 R4_PD19.1@8010.57,14696.99 ; v1(8715,14725) 8743,14725 8750.57,14717.43 R4_PD20.1@8750.57,14696.99
  MidLayer1 w8: v1(6495,14725) v1(7025,14725) v1(7235,14725) v1(7765,14725) v1(7975,14725) v1(8505,14725) v1(8715,14725) v1(9245,14725) 9345,14725 9370,14700 9370,14430 JP1.3@9445,14355
  BottomLayer w8: R4_PD24.1@6989.43,14696.99 6989.43,14718 6996.43,14725 v1(7025,14725) ; R4_PD23.1@7729.43,14696.99 7729.43,14718 7736.43,14725 v1(7765,14725) ; R4_PD22.1@8469.43,14696.99 8469.43,14718 8476.43,14725 v1(8505,14725) ; R4_PD21.1@9209.43,14696.99 9209.43,14718 9216.43,14725 v1(9245,14725)
OFF4: JP1.4 R4_PD25.1 R4_PD26.1 R4_PD27.1 R4_PD28.1 R4_PD29.1 R4_PD30.1 R4_PD31.1 R4_PD32.1 | length 4310.6
  TopLayer w8: v1(6495,15385) 6523,15385 6530.57,15377.43 R4_PD25.1@6530.57,15356.99 ; v1(7235,15385) 7263,15385 7270.57,15377.43 R4_PD26.1@7270.57,15356.99 ; v1(7975,15385) 8003,15385 8010.57,15377.43 R4_PD27.1@8010.57,15356.99 ; v1(8715,15385) 8743,15385 8750.57,15377.43 R4_PD28.1@8750.57,15356.99
  MidLayer1 w8: v1(6495,15385) v1(7025,15385) v1(7235,15385) v1(7765,15385) v1(7975,15385) v1(8505,15385) v1(8715,15385) v1(9245,15385) 9370,15385 9395,15360 9395,14505 JP1.4@9445,14455
  BottomLayer w8: R4_PD32.1@6989.43,15356.99 6989.43,15378 6996.43,15385 v1(7025,15385) ; R4_PD31.1@7729.43,15356.99 7729.43,15378 7736.43,15385 v1(7765,15385) ; R4_PD30.1@8469.43,15356.99 8469.43,15378 8476.43,15385 v1(8505,15385) ; R4_PD29.1@9209.43,15356.99 9209.43,15378 9216.43,15385 v1(9245,15385)
P1_BANK1: C1_PD1.2 JP2_BANK1.1 R3_PD1.2 | length 559.7
  TopLayer w4: C1_PD1.2@6455,13480 6515,13420 6550,13420 6570,13400 v1(6570,13375)
  TopLayer w8: v1(6570,13375) 6572,13377 R3_PD1.2@6622.14,13377
  MidLayer1 w4: v2(6370,13340) 6554,13340 6570,13356 v1(6570,13375)
  BottomLayer w4: JP2_BANK1.1@6333.98,13412.68 6333.98,13398.98 6320,13385 6320,13375 6355,13340 v2(6370,13340)
P1_BANK2: C1_PD9.2 JP2_BANK2.1 R3_PD9.2 | length 633.9
  TopLayer w4: C1_PD9.2@6455,14140 6515,14080 6550,14080 6570,14060 v1(6570,14035)
  TopLayer w8: v1(6570,14035) 6572,14037 R3_PD9.2@6622.14,14037
  MidLayer1 w4: v2(6370,14000) 6420,13950 6560,13950 6570,13960 v1(6570,14035)
  BottomLayer w4: JP2_BANK2.1@6333.98,14072.68 6333.98,14058.98 6320,14045 6320,14035 6355,14000 v2(6370,14000)
P1_BANK3: C1_PD17.2 JP2_BANK3.1 R3_PD17.2 | length 633.9
  TopLayer w4: C1_PD17.2@6455,14800 6515,14740 6550,14740 6570,14720 v1(6570,14695)
  TopLayer w8: v1(6570,14695) 6572,14697 R3_PD17.2@6622.14,14697
  MidLayer1 w4: v2(6370,14660) 6420,14610 6560,14610 6570,14620 v1(6570,14695)
  BottomLayer w4: JP2_BANK3.1@6333.98,14732.68 6333.98,14718.98 6320,14705 6320,14695 6355,14660 v2(6370,14660)
P1_BANK4: C1_PD25.2 JP2_BANK4.1 R3_PD25.2 | length 633.9
  TopLayer w4: C1_PD25.2@6455,15460 6515,15400 6550,15400 6570,15380 v1(6570,15355)
  TopLayer w8: v1(6570,15355) 6572,15357 R3_PD25.2@6622.14,15357
  MidLayer1 w4: v2(6370,15320) 6420,15270 6560,15270 6570,15280 v1(6570,15355)
  BottomLayer w4: JP2_BANK4.1@6333.98,15392.68 6333.98,15378.98 6320,15365 6320,15355 6355,15320 v2(6370,15320)
P2_BANK1: C1_PD2.2 JP2_BANK1.2 R3_PD2.2 | length 1455.4
  TopLayer w4: C1_PD2.2@7195,13480 7255,13420 7290,13420 7310,13400 v1(7310,13375)
  TopLayer w8: v1(7310,13375) 7312,13377 R3_PD2.2@7362.14,13377
  MidLayer1 w4: v2(6340,13380) 6340,13325 6367.38,13297.62 6382.38,13297.62 6400,13280 6945,13280 6955,13290 7300,13290 7310,13300 v1(7310,13375)
  BottomLayer w4: JP2_BANK1.2@6333.98,13432.36 6362.64,13432.36 6370,13425 6370,13406.31 6357,13393.31 6357,13387 6350,13380 v2(6340,13380)
P2_BANK2: C1_PD10.2 JP2_BANK2.2 R3_PD10.2 | length 1463.7
  TopLayer w4: C1_PD10.2@7195,14140 7255,14080 7290,14080 7310,14060 v1(7310,14035)
  TopLayer w8: v1(7310,14035) 7312,14037 R3_PD10.2@7362.14,14037
  MidLayer1 w4: v2(6340,14040) 6340,13985 6367.38,13957.62 6382.38,13957.62 6410,13930 6570,13930 6580,13940 6945,13940 6955,13950 7300,13950 7310,13960 v1(7310,14035)
  BottomLayer w4: JP2_BANK2.2@6333.98,14092.36 6362.64,14092.36 6370,14085 6370,14066.31 6357,14053.31 6357,14047 6350,14040 v2(6340,14040)
P2_BANK3: C1_PD18.2 JP2_BANK3.2 R3_PD18.2 | length 1463.7
  TopLayer w4: C1_PD18.2@7195,14800 7255,14740 7290,14740 7310,14720 v1(7310,14695)
  TopLayer w8: v1(7310,14695) 7312,14697 R3_PD18.2@7362.14,14697
  MidLayer1 w4: v2(6340,14700) 6340,14645 6367.38,14617.62 6382.38,14617.62 6410,14590 6570,14590 6580,14600 6945,14600 6955,14610 7300,14610 7310,14620 v1(7310,14695)
  BottomLayer w4: JP2_BANK3.2@6333.98,14752.36 6362.64,14752.36 6370,14745 6370,14726.31 6357,14713.31 6357,14707 6350,14700 v2(6340,14700)
P2_BANK4: C1_PD26.2 JP2_BANK4.2 R3_PD26.2 | length 1463.7
  TopLayer w4: C1_PD26.2@7195,15460 7255,15400 7290,15400 7310,15380 v1(7310,15355)
  TopLayer w8: v1(7310,15355) 7312,15357 R3_PD26.2@7362.14,15357
  MidLayer1 w4: v2(6340,15360) 6340,15305 6367.38,15277.62 6382.38,15277.62 6410,15250 6570,15250 6580,15260 6945,15260 6955,15270 7300,15270 7310,15280 v1(7310,15355)
  BottomLayer w4: JP2_BANK4.2@6333.98,15412.36 6362.64,15412.36 6370,15405 6370,15386.31 6357,15373.31 6357,15367 6350,15360 v2(6340,15360)
P3_BANK1: C1_PD3.2 JP2_BANK1.3 R3_PD3.2 | length 2287.1
  TopLayer w4: C1_PD3.2@7935,13480 7995,13420 8030,13420 8050,13400 v1(8050,13375)
  TopLayer w8: v1(8050,13375) 8052,13377 R3_PD3.2@8102.14,13377
  MidLayer1 w4: v1@6280,13430 6282.5,13427.5 6300,13410 6300,13310 6335,13275 6370,13275 6385,13260 6955,13260 6965,13270 7310,13270 7320,13280 7685,13280 7695,13290 8040,13290 8050,13300 v1(8050,13375)
  BottomLayer w4: v1@6280,13430 v1@6282.5,13432.5 ; v1(6285,13430) 6285,13445 6292.05,13452.05 JP2_BANK1.3@6333.98,13452.05
P3_BANK2: C1_PD11.2 JP2_BANK2.3 R3_PD11.2 | length 2295.4
  TopLayer w4: C1_PD11.2@7935,14140 7995,14080 8030,14080 8050,14060 v1(8050,14035)
  TopLayer w8: v1(8050,14035) 8052,14037 R3_PD11.2@8102.14,14037
  MidLayer1 w4: v1@6280,14090 6282.5,14087.5 6300,14070 6300,13970 6335,13935 6370,13935 6395,13910 6580,13910 6590,13920 6955,13920 6965,13930 7310,13930 7320,13940 7685,13940 7695,13950 8040,13950 8050,13960 v1(8050,14035)
  BottomLayer w4: v1@6280,14090 v1@6282.5,14092.5 ; v1(6285,14090) 6285,14105 6292.05,14112.05 JP2_BANK2.3@6333.98,14112.05
P3_BANK3: C1_PD19.2 JP2_BANK3.3 R3_PD19.2 | length 2295.4
  TopLayer w4: C1_PD19.2@7935,14800 7995,14740 8030,14740 8050,14720 v1(8050,14695)
  TopLayer w8: v1(8050,14695) 8052,14697 R3_PD19.2@8102.14,14697
  MidLayer1 w4: v1@6280,14750 6282.5,14747.5 6300,14730 6300,14630 6335,14595 6370,14595 6395,14570 6580,14570 6590,14580 6955,14580 6965,14590 7310,14590 7320,14600 7685,14600 7695,14610 8040,14610 8050,14620 v1(8050,14695)
  BottomLayer w4: v1@6280,14750 v1@6282.5,14752.5 ; v1(6285,14750) 6285,14765 6292.05,14772.05 JP2_BANK3.3@6333.98,14772.05
P3_BANK4: C1_PD27.2 JP2_BANK4.3 R3_PD27.2 | length 2295.4
  TopLayer w4: C1_PD27.2@7935,15460 7995,15400 8030,15400 8050,15380 v1(8050,15355)
  TopLayer w8: v1(8050,15355) 8052,15357 R3_PD27.2@8102.14,15357
  MidLayer1 w4: v1@6280,15410 6282.5,15407.5 6300,15390 6300,15290 6335,15255 6370,15255 6395,15230 6580,15230 6590,15240 6955,15240 6965,15250 7310,15250 7320,15260 7685,15260 7695,15270 8040,15270 8050,15280 v1(8050,15355)
  BottomLayer w4: v1@6280,15410 v1@6282.5,15412.5 ; v1(6285,15410) 6285,15425 6292.05,15432.05 JP2_BANK4.3@6333.98,15432.05
P4_BANK1: C1_PD4.2 JP2_BANK1.4 R3_PD4.2 | length 3112.1
  TopLayer w4: C1_PD4.2@8675,13480 8735,13420 8770,13420 8790,13400 v1(8790,13375)
  TopLayer w8: v1(8790,13375) 8792,13377 R3_PD4.2@8842.14,13377
  MidLayer1 w4: v2(6271.73,13471.73) 6255,13455 6255,13415 6280,13390 6280,13300 6325,13255 6360,13255 6375,13240 6965,13240 6975,13250 7320,13250 7330,13260 7695,13260 7705,13270 8050,13270 8060,13280 8425,13280 8435,13290 8780,13290 8790,13300 v1(8790,13375)
  BottomLayer w4: v2(6271.73,13471.73) JP2_BANK1.4@6333.98,13471.73
P4_BANK2: C1_PD12.2 JP2_BANK2.4 R3_PD12.2 | length 3120.4
  TopLayer w4: C1_PD12.2@8675,14140 8735,14080 8770,14080 8790,14060 v1(8790,14035)
  TopLayer w8: v1(8790,14035) 8792,14037 R3_PD12.2@8842.14,14037
  MidLayer1 w4: v2(6271.73,14131.73) 6255,14115 6255,14075 6280,14050 6280,13960 6325,13915 6360,13915 6385,13890 6590,13890 6600,13900 6965,13900 6975,13910 7320,13910 7330,13920 7695,13920 7705,13930 8050,13930 8060,13940 8425,13940 8435,13950 8780,13950 8790,13960 v1(8790,14035)
  BottomLayer w4: v2(6271.73,14131.73) JP2_BANK2.4@6333.98,14131.73
P4_BANK3: C1_PD20.2 JP2_BANK3.4 R3_PD20.2 | length 3120.4
  TopLayer w4: C1_PD20.2@8675,14800 8735,14740 8770,14740 8790,14720 v1(8790,14695)
  TopLayer w8: v1(8790,14695) 8792,14697 R3_PD20.2@8842.14,14697
  MidLayer1 w4: v2(6271.73,14791.73) 6255,14775 6255,14735 6280,14710 6280,14620 6325,14575 6360,14575 6385,14550 6590,14550 6600,14560 6965,14560 6975,14570 7320,14570 7330,14580 7695,14580 7705,14590 8050,14590 8060,14600 8425,14600 8435,14610 8780,14610 8790,14620 v1(8790,14695)
  BottomLayer w4: v2(6271.73,14791.73) JP2_BANK3.4@6333.98,14791.73
P4_BANK4: C1_PD28.2 JP2_BANK4.4 R3_PD28.2 | length 3120.4
  TopLayer w4: C1_PD28.2@8675,15460 8735,15400 8770,15400 8790,15380 v1(8790,15355)
  TopLayer w8: v1(8790,15355) 8792,15357 R3_PD28.2@8842.14,15357
  MidLayer1 w4: v2(6271.73,15451.73) 6255,15435 6255,15395 6280,15370 6280,15280 6325,15235 6360,15235 6385,15210 6590,15210 6600,15220 6965,15220 6975,15230 7320,15230 7330,15240 7695,15240 7705,15250 8050,15250 8060,15260 8425,15260 8435,15270 8780,15270 8790,15280 v1(8790,15355)
  BottomLayer w4: v2(6271.73,15451.73) JP2_BANK4.4@6333.98,15451.73
P5_BANK1: C1_PD5.2 JP2_BANK1.5 R3_PD5.2 | length 3610.3
  MidLayer1 w4: v2(6270,13530) 6245,13505 6245,13410 6270,13385 6270,13295 6320,13245 6355,13245 6370,13230 6970,13230 6980,13240 7325,13240 7335,13250 7700,13250 7710,13260 8055,13260 8065,13270 8430,13270 8440,13280 8785,13280 8795,13290 9160,13290 9170,13300 v1(9170,13375)
  BottomLayer w4: v2(6270,13530) 6270,13500 6278.58,13491.42 JP2_BANK1.5@6333.98,13491.42 ; v1(9170,13375) 9170,13400 9190,13420 9225,13420 C1_PD5.2@9285,13480
  BottomLayer w8: R3_PD5.2@9117.86,13377 9168,13377 v1(9170,13375)
P5_BANK2: C1_PD13.2 JP2_BANK2.5 R3_PD13.2 | length 3618.6
  MidLayer1 w4: v2(6270,14190) 6245,14165 6245,14070 6270,14045 6270,13955 6320,13905 6355,13905 6380,13880 6595,13880 6605,13890 6970,13890 6980,13900 7325,13900 7335,13910 7700,13910 7710,13920 8055,13920 8065,13930 8430,13930 8440,13940 8785,13940 8795,13950 9160,13950 9170,13960 v1(9170,14035)
  BottomLayer w4: v2(6270,14190) 6270,14160 6278.58,14151.42 JP2_BANK2.5@6333.98,14151.42 ; v1(9170,14035) 9170,14060 9190,14080 9225,14080 C1_PD13.2@9285,14140
  BottomLayer w8: R3_PD13.2@9117.86,14037 9168,14037 v1(9170,14035)
P5_BANK3: C1_PD21.2 JP2_BANK3.5 R3_PD21.2 | length 3618.6
  MidLayer1 w4: v2(6270,14850) 6245,14825 6245,14730 6270,14705 6270,14615 6320,14565 6355,14565 6380,14540 6595,14540 6605,14550 6970,14550 6980,14560 7325,14560 7335,14570 7700,14570 7710,14580 8055,14580 8065,14590 8430,14590 8440,14600 8785,14600 8795,14610 9160,14610 9170,14620 v1(9170,14695)
  BottomLayer w4: v2(6270,14850) 6270,14820 6278.58,14811.42 JP2_BANK3.5@6333.98,14811.42 ; v1(9170,14695) 9170,14720 9190,14740 9225,14740 C1_PD21.2@9285,14800
  BottomLayer w8: R3_PD21.2@9117.86,14697 9168,14697 v1(9170,14695)
P5_BANK4: C1_PD29.2 JP2_BANK4.5 R3_PD29.2 | length 3618.6
  MidLayer1 w4: v2(6270,15510) 6245,15485 6245,15390 6270,15365 6270,15275 6320,15225 6355,15225 6380,15200 6595,15200 6605,15210 6970,15210 6980,15220 7325,15220 7335,15230 7700,15230 7710,15240 8055,15240 8065,15250 8430,15250 8440,15260 8785,15260 8795,15270 9160,15270 9170,15280 v1(9170,15355)
  BottomLayer w4: v2(6270,15510) 6270,15480 6278.58,15471.42 JP2_BANK4.5@6333.98,15471.42 ; v1(9170,15355) 9170,15380 9190,15400 9225,15400 C1_PD29.2@9285,15460
  BottomLayer w8: R3_PD29.2@9117.86,15357 9168,15357 v1(9170,15355)
P6_BANK1: C1_PD6.2 JP2_BANK1.6 R3_PD6.2 | length 2753.2
  MidLayer1 w4: v1(6290,13510) 6290,13465 6265,13440 6265,13420 6290,13395 6290,13305 6330,13265 6365,13265 6380,13250 6960,13250 6970,13260 7315,13260 7325,13270 7690,13270 7700,13280 8045,13280 8055,13290 8420,13290 8430,13300 v1(8430,13375)
  BottomLayer w4: v1@6291.1,13511.1 JP2_BANK1.6@6333.98,13511.1 ; v1(8430,13375) 8430,13400 8450,13420 8485,13420 C1_PD6.2@8545,13480
  BottomLayer w8: R3_PD6.2@8377.86,13377 8428,13377 v1(8430,13375)
P6_BANK2: C1_PD14.2 JP2_BANK2.6 R3_PD14.2 | length 2761.5
  MidLayer1 w4: v1(6290,14170) 6290,14125 6265,14100 6265,14080 6290,14055 6290,13965 6330,13925 6365,13925 6390,13900 6585,13900 6595,13910 6960,13910 6970,13920 7315,13920 7325,13930 7690,13930 7700,13940 8045,13940 8055,13950 8420,13950 8430,13960 v1(8430,14035)
  BottomLayer w4: v1@6291.1,14171.1 JP2_BANK2.6@6333.98,14171.1 ; v1(8430,14035) 8430,14060 8450,14080 8485,14080 C1_PD14.2@8545,14140
  BottomLayer w8: R3_PD14.2@8377.86,14037 8428,14037 v1(8430,14035)
P6_BANK3: C1_PD22.2 JP2_BANK3.6 R3_PD22.2 | length 2761.5
  MidLayer1 w4: v1(6290,14830) 6290,14785 6265,14760 6265,14740 6290,14715 6290,14625 6330,14585 6365,14585 6390,14560 6585,14560 6595,14570 6960,14570 6970,14580 7315,14580 7325,14590 7690,14590 7700,14600 8045,14600 8055,14610 8420,14610 8430,14620 v1(8430,14695)
  BottomLayer w4: v1@6291.1,14831.1 JP2_BANK3.6@6333.98,14831.1 ; v1(8430,14695) 8430,14720 8450,14740 8485,14740 C1_PD22.2@8545,14800
  BottomLayer w8: R3_PD22.2@8377.86,14697 8428,14697 v1(8430,14695)
P6_BANK4: C1_PD30.2 JP2_BANK4.6 R3_PD30.2 | length 2761.5
  MidLayer1 w4: v1(6290,15490) 6290,15445 6265,15420 6265,15400 6290,15375 6290,15285 6330,15245 6365,15245 6390,15220 6585,15220 6595,15230 6960,15230 6970,15240 7315,15240 7325,15250 7690,15250 7700,15260 8045,15260 8055,15270 8420,15270 8430,15280 v1(8430,15355)
  BottomLayer w4: v1@6291.1,15491.1 JP2_BANK4.6@6333.98,15491.1 ; v1(8430,15355) 8430,15380 8450,15400 8485,15400 C1_PD30.2@8545,15460
  BottomLayer w8: R3_PD30.2@8377.86,15357 8428,15357 v1(8430,15355)
P7_BANK1: C1_PD7.2 JP2_BANK1.7 R3_PD7.2 | length 2052.5
  MidLayer1 w4: v2(6320,13315) 6350,13285 6380,13285 6395,13270 6950,13270 6960,13280 7305,13280 7315,13290 7680,13290 7690,13300 v1(7690,13375)
  BottomLayer w4: v2(6320,13315) 6380,13315 6395,13330 6395,13350 6385,13360 6380,13360 6365,13375 6365,13390 6385,13410 6385,13520 6374.21,13530.79 JP2_BANK1.7@6333.98,13530.79 ; v1(7690,13375) 7690,13400 7710,13420 7745,13420 C1_PD7.2@7805,13480
  BottomLayer w8: R3_PD7.2@7637.86,13377 7688,13377 v1(7690,13375)
P7_BANK2: C1_PD15.2 JP2_BANK2.7 R3_PD15.2 | length 2060.8
  MidLayer1 w4: v2(6320,13975) 6350,13945 6380,13945 6405,13920 6575,13920 6585,13930 6950,13930 6960,13940 7305,13940 7315,13950 7680,13950 7690,13960 v1(7690,14035)
  BottomLayer w4: v2(6320,13975) 6380,13975 6395,13990 6395,14010 6385,14020 6380,14020 6365,14035 6365,14050 6385,14070 6385,14180 6374.21,14190.79 JP2_BANK2.7@6333.98,14190.79 ; v1(7690,14035) 7690,14060 7710,14080 7745,14080 C1_PD15.2@7805,14140
  BottomLayer w8: R3_PD15.2@7637.86,14037 7688,14037 v1(7690,14035)
P7_BANK3: C1_PD23.2 JP2_BANK3.7 R3_PD23.2 | length 2060.8
  MidLayer1 w4: v2(6320,14635) 6350,14605 6380,14605 6405,14580 6575,14580 6585,14590 6950,14590 6960,14600 7305,14600 7315,14610 7680,14610 7690,14620 v1(7690,14695)
  BottomLayer w4: v2(6320,14635) 6380,14635 6395,14650 6395,14670 6385,14680 6380,14680 6365,14695 6365,14710 6385,14730 6385,14840 6374.21,14850.79 JP2_BANK3.7@6333.98,14850.79 ; v1(7690,14695) 7690,14720 7710,14740 7745,14740 C1_PD23.2@7805,14800
  BottomLayer w8: R3_PD23.2@7637.86,14697 7688,14697 v1(7690,14695)
P7_BANK4: C1_PD31.2 JP2_BANK4.7 R3_PD31.2 | length 2060.8
  MidLayer1 w4: v2(6320,15295) 6350,15265 6380,15265 6405,15240 6575,15240 6585,15250 6950,15250 6960,15260 7305,15260 7315,15270 7680,15270 7690,15280 v1(7690,15355)
  BottomLayer w4: v2(6320,15295) 6380,15295 6395,15310 6395,15330 6385,15340 6380,15340 6365,15355 6365,15370 6385,15390 6385,15500 6374.21,15510.79 JP2_BANK4.7@6333.98,15510.79 ; v1(7690,15355) 7690,15380 7710,15400 7745,15400 C1_PD31.2@7805,15460
  BottomLayer w8: R3_PD31.2@7637.86,15357 7688,15357 v1(7690,15355)
P8_BANK1: C1_PD8.2 JP2_BANK1.8 R3_PD8.2 | length 1212.9
  MidLayer1 w4: v1(6385,13380) 6350,13345 6350,13330 6370,13310 6385,13310 6405,13290 6940,13290 6950,13300 v1(6950,13375)
  BottomLayer w4: JP2_BANK1.8@6333.98,13550.47 6379.53,13550.47 6395,13535 6395,13390 v1(6385,13380) ; v1(6950,13375) 6950,13400 6970,13420 7005,13420 C1_PD8.2@7065,13480
  BottomLayer w8: R3_PD8.2@6897.86,13377 6948,13377 v1(6950,13375)
P8_BANK2: C1_PD16.2 JP2_BANK2.8 R3_PD16.2 | length 1221.2
  MidLayer1 w4: v1(6385,14040) 6350,14005 6350,13990 6370,13970 6385,13970 6415,13940 6565,13940 6575,13950 6940,13950 6950,13960 v1(6950,14035)
  BottomLayer w4: JP2_BANK2.8@6333.98,14210.47 6379.53,14210.47 6395,14195 6395,14050 v1(6385,14040) ; v1(6950,14035) 6950,14060 6970,14080 7005,14080 C1_PD16.2@7065,14140
  BottomLayer w8: R3_PD16.2@6897.86,14037 6948,14037 v1(6950,14035)
P8_BANK3: C1_PD24.2 JP2_BANK3.8 R3_PD24.2 | length 1221.2
  MidLayer1 w4: v1(6385,14700) 6350,14665 6350,14650 6370,14630 6385,14630 6415,14600 6565,14600 6575,14610 6940,14610 6950,14620 v1(6950,14695)
  BottomLayer w4: JP2_BANK3.8@6333.98,14870.47 6379.53,14870.47 6395,14855 6395,14710 v1(6385,14700) ; v1(6950,14695) 6950,14720 6970,14740 7005,14740 C1_PD24.2@7065,14800
  BottomLayer w8: R3_PD24.2@6897.86,14697 6948,14697 v1(6950,14695)
P8_BANK4: C1_PD32.2 JP2_BANK4.8 R3_PD32.2 | length 1221.2
  MidLayer1 w4: v1(6385,15360) 6350,15325 6350,15310 6370,15290 6385,15290 6415,15260 6565,15260 6575,15270 6940,15270 6950,15280 v1(6950,15355)
  BottomLayer w4: JP2_BANK4.8@6333.98,15530.47 6379.53,15530.47 6395,15515 6395,15370 v1(6385,15360) ; v1(6950,15355) 6950,15380 6970,15400 7005,15400 C1_PD32.2@7065,15460
  BottomLayer w8: R3_PD32.2@6897.86,15357 6948,15357 v1(6950,15355)
S_DIODE_PD1: C4_PD1.2 D1_PD1.1 D2_PD1.2 U1_PD1.7 | length 661.7
  TopLayer w4: D1_PD1.1@6815.01,13825 6862.35,13825 ; U1_PD1.7@6862.35,13750 6862.35,13825 ; C4_PD1.2@6969.99,13470 6969.99,13504.99 7009,13544 7009,13622 7020,13633 7020,13690 ; D2_PD1.2@7070,13690.01 7020.01,13690.01 ; 6862.35,13825 6885,13825 6890,13820 6950,13820 7020,13750 7020,13690.02
S_DIODE_PD2: C4_PD2.2 D1_PD2.1 D2_PD2.2 U1_PD2.7 | length 661.7
  TopLayer w4: D1_PD2.1@7555.01,13825 7602.35,13825 ; U1_PD2.7@7602.35,13750 7602.35,13825 ; C4_PD2.2@7709.99,13470 7709.99,13504.99 7749,13544 7749,13622 7760,13633 7760,13690 ; D2_PD2.2@7810,13690.01 7760.01,13690.01 ; 7602.35,13825 7625,13825 7630,13820 7690,13820 7760,13750 7760,13690.02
